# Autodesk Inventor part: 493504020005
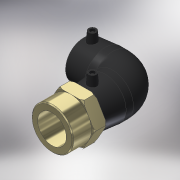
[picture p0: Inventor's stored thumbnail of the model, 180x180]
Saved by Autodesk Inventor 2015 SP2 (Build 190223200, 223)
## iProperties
Created: 2017-06
Part Number: 493504020005
Material: Generic
Description: PLASSON 90° ELBOW FEMALE TRANSITION 20-1/2''
Document SubType Name: Modeling
Designer: KIM
Mass: 70.2573 g
Surface Area: 237.001 cm^2
Volume: 70.2573 cm^3
Density: 1 g/cm^3
Appearance: Rubber - Black
Author: KIM
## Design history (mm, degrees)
derived "493504.ipt"
feature "Solid1::493504.ipt"
tag "TaggingFeature1"
body "Solid1"
other parameters: "d2" = 32, "d4" = 22, "d5" = 28.8, "d8" = 168 deg, "d10" = 14, "d11" = 4.66667, "d29" = 38, "d30" = 15, "d31" = 36.3, "d34" = 5 deg, "d41" = 4, "d42" = 14, "d43" = 0, "d50" = 17, "d51" = 14, "d52" = 35, "d54" = 90 deg, "d58" = 35, "d59" = 0, "d61" = 90 deg, "d86" = 3, "d87" = 0, "d93" = 0.1, "d96" = 18.631, "d97" = 14, "d99" = 32, "d100" = 16, "d107" = 8, "d108" = 0, "d109" = 0.6, "d112" = 45 deg, "d113" = 45 deg, "d114" = 1, "L_" = 86, "L_1" = 35, "D_" = 14, "A_" = 38, "d_2" = 12, "D_1" = 32, "Rp_" = 18.631
